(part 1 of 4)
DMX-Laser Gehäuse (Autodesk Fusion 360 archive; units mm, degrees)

design "Laser Gehäuse" references "Laserhalter", "Spiegelaufbau", "Leiterplatte", "Leiterplatte 3 Laser"
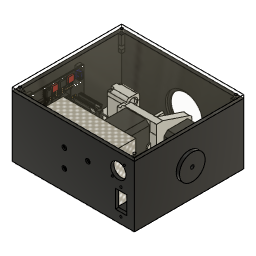
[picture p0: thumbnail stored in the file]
component_insert "Komponente einfügen1"
sketch "Skizze1" plane through (0, 0, 0) normal (0, 0, 1) x axis (1, 0, 0)
  line L1 (190, 0) -> (0, 0)
  line L2 (190, 150) -> (190, 0)
  line L3 (0, 150) -> (190, 150)
  line L4 (0, 0) -> (0, 150)
  point P1 (0, 0)
  point P2 (0, 0)
  horizontal L1
  vertical L2
  horizontal L3
  vertical L4
  coincident P1 P2
extrude "Extrusion1" new body sketch "Skizze1" along normal blind 5
sketch "Skizze2" plane through (0, 0, 5) normal (0, 0, 1) x axis (-1, 0, 0)
  line L1 (0, 0) -> (0, -150)
  line L2 (-190, 0) -> (0, 0)
  line L3 (-190, -150) -> (-190, 0)
  line L4 (0, -150) -> (-190, -150)
  line L5 (-190, 0) -> (0, 0)
  line L6 (-190, -150) -> (-190, 0)
  line L7 (0, -150) -> (-190, -150)
  line L8 (0, 0) -> (0, -150)
  line L9 (-185, -5) -> (-5, -5)
  line L10 (-185, -145) -> (-185, -5)
  line L11 (-5, -145) -> (-185, -145)
  line L12 (-5, -5) -> (-5, -145)
  point P5 (-190, -150)
  point P8 (-190, -150)
  point P1 (0, 0)
  point P6 (0, 0)
  horizontal L5
  vertical L6
  horizontal L7
  vertical L8
  coincident P5 P8
  coincident P1 P6
  horizontal L9
  vertical L10
  horizontal L11
  vertical L12
extrude "Extrusion2" add sketch "Skizze2" along normal blind 90
sketch "Skizze3" plane through (0, 0, 95) normal (0, 0, 1) x axis (-1, 0, 0)
  line L1 (-5, -145) -> (-5, -5)
  line L2 (-185, -145) -> (-5, -145)
  line L3 (-185, -5) -> (-185, -145)
  line L4 (-5, -5) -> (-185, -5)
  line L5 (0, 0) -> (0, -150)
  line L6 (-190, 0) -> (0, 0)
  line L7 (-190, -150) -> (-190, 0)
  line L8 (0, -150) -> (-190, -150)
  line L9 (-190, 0) -> (0, 0)
  line L10 (-190, -150) -> (-190, 0)
  line L11 (0, -150) -> (-190, -150)
  line L12 (0, 0) -> (0, -150)
  point P9 (-190, -150)
  point P12 (-190, -150)
  point P7 (0, 0)
  point P10 (0, 0)
  horizontal L9
  vertical L10
  horizontal L11
  vertical L12
  coincident P9 P12
  coincident P7 P10
extrude "Extrusion3" new body sketch "Skizze3" along normal blind 5
remove_instance "Exemplar entfernen"
sketch "Skizze4" plane through (0, 0, 95) normal (0, 0, 1) x axis (-1, 0, 0)
  line L1 (-5, -145) -> (-5, -5)
  line L2 (-185, -145) -> (-5, -145)
  line L3 (-185, -5) -> (-185, -145)
  line L4 (-5, -5) -> (-185, -5)
  line L5 (0, 0) -> (0, -150)
  line L6 (-190, 0) -> (0, 0)
  line L7 (-190, -150) -> (-190, 0)
  line L8 (0, -150) -> (-190, -150)
  line L9 (-180, -5) -> (-185, -5)
  line L10 (-180, -10) -> (-180, -5)
  line L11 (-185, -10) -> (-180, -10)
  line L12 (-185, -5) -> (-185, -10)
  line L13 (-180, -145) -> (-185, -145)
  line L14 (-180, -140) -> (-180, -145)
  line L15 (-185, -140) -> (-180, -140)
  line L16 (-185, -145) -> (-185, -140)
  line L17 (-10, -145) -> (-5, -145)
  line L18 (-10, -140) -> (-10, -145)
  line L19 (-5, -140) -> (-10, -140)
  line L20 (-5, -145) -> (-5, -140)
  line L21 (-10, -5) -> (-5, -5)
  line L22 (-10, -10) -> (-10, -5)
  line L23 (-5, -10) -> (-10, -10)
  line L24 (-5, -5) -> (-5, -10)
  point P5 (-185, -5)
  point P10 (-185, -5)
  point P4 (-185, -145)
  point P14 (-185, -145)
  point P3 (-5, -145)
  point P18 (-5, -145)
  point P2 (-5, -5)
  point P22 (-5, -5)
  horizontal L9
  vertical L10
  horizontal L11
  vertical L12
  coincident P5 P10
  horizontal L13
  vertical L14
  horizontal L15
  vertical L16
  coincident P4 P14
  horizontal L17
  vertical L18
  horizontal L19
  vertical L20
  coincident P3 P18
  horizontal L21
  vertical L22
  horizontal L23
  vertical L24
  coincident P2 P22
extrude "Extrusion4" add sketch "Skizze4" profile of L1 L2 L3 L4 L9 L10 L11 L12 L13 L14 L15 L16 L17 L18 L19 L20 L21 L22 L23 L24 against normal blind 25
sketch "Skizze5" plane through (0, 0, 95) normal (0, 0, 1) x axis (-1, 0, 0)
  line L1 (-5, -140) -> (-5, -10)
  line L2 (-10, -140) -> (-5, -140)
  line L3 (-10, -145) -> (-10, -140)
  line L4 (-180, -145) -> (-10, -145)
  line L5 (-180, -140) -> (-180, -145)
  line L6 (-185, -140) -> (-180, -140)
  line L7 (-185, -10) -> (-185, -140)
  line L8 (-180, -10) -> (-185, -10)
  line L9 (-180, -5) -> (-180, -10)
  line L10 (-10, -5) -> (-180, -5)
  line L11 (-10, -10) -> (-10, -5)
  line L12 (-5, -10) -> (-10, -10)
  line L13 (0, 0) -> (0, -150)
  line L14 (-190, 0) -> (0, 0)
  line L15 (-190, -150) -> (-190, 0)
  line L16 (0, -150) -> (-190, -150)
  line L17 (-2, -10) -> (-10, -10)
  line L18 (-2, -2) -> (-2, -10)
  line L19 (-10, -2) -> (-2, -2)
  line L20 (-10, -10) -> (-10, -2)
  line L21 (-2, -140) -> (-10, -140)
  line L22 (-2, -148) -> (-2, -140)
  line L23 (-10, -148) -> (-2, -148)
  line L24 (-10, -140) -> (-10, -148)
  line L25 (-188, -140) -> (-180, -140)
  line L26 (-188, -148) -> (-188, -140)
  line L27 (-180, -148) -> (-188, -148)
  line L28 (-180, -140) -> (-180, -148)
  line L29 (-188, -10) -> (-180, -10)
  line L30 (-188, -2) -> (-188, -10)
  line L31 (-180, -2) -> (-188, -2)
  line L32 (-180, -10) -> (-180, -2)
  point P13 (-10, -10)
  point P18 (-10, -10)
  point P4 (-10, -140)
  point P22 (-10, -140)
  point P7 (-180, -140)
  point P26 (-180, -140)
  point P10 (-180, -10)
  point P30 (-180, -10)
  horizontal L17
  vertical L18
  horizontal L19
  vertical L20
  coincident P13 P18
  horizontal L21
  vertical L22
  horizontal L23
  vertical L24
  coincident P4 P22
  horizontal L25
  vertical L26
  horizontal L27
  vertical L28
  coincident P7 P26
  horizontal L29
  vertical L30
  horizontal L31
  vertical L32
  coincident P10 P30
extrude "Extrusion5" new body sketch "Skizze5" profile of L2 L3 L5 L6 L8 L9 L11 L12 L17 L18 L19 L20 L21 L22 L23 L24 L25 L26 L27 L28 L29 L30 L31 L32 along normal blind 5
move "Verschieben1"
combine "Kombinieren1" sketch "Skizze7"
sketch "Skizze6" plane through (0, 0, 95) normal (0, 0, 1) x axis (-1, 0, 0)
  line L1 (-5, -140) -> (-5, -10)
  line L2 (-10, -140) -> (-5, -140)
  line L3 (-10, -145) -> (-10, -140)
  line L4 (-180, -145) -> (-10, -145)
  line L5 (-180, -140) -> (-180, -145)
  line L6 (-185, -140) -> (-180, -140)
  line L7 (-185, -10) -> (-185, -140)
  line L8 (-180, -10) -> (-185, -10)
  line L9 (-180, -5) -> (-180, -10)
  line L10 (-10, -5) -> (-180, -5)
  line L11 (-10, -10) -> (-10, -5)
  line L12 (-5, -10) -> (-10, -10)
  line L13 (0, 0) -> (0, -150)
  line L14 (-190, 0) -> (0, 0)
  line L15 (-190, -150) -> (-190, 0)
  line L16 (0, -150) -> (-190, -150)
  circle C1 centre (-184, -6) radius 2
  circle C2 centre (-6, -6) radius 2
  circle C3 centre (-6, -144) radius 2
  circle C4 centre (-184, -144) radius 2
  dimension "d11" diameter C2 = 4
  dimension "d12" diameter C3 = 4
  dimension "d13" diameter C4 = 4
extrude "Extrusion6" cut sketch "Skizze6" profile of C1 C2 C3 C4 against normal blind 18
extrude "Extrusion7" cut sketch "Skizze6" profile of C1 C2 C3 C4 along normal blind 20
sketch "Skizze7" plane through (5, 0, 0) normal (1, 0, 0) x axis (0, 1, 0)
  line L1 (5, 70) -> (10, 70)
  line L2 (5, 5) -> (5, 70)
  line L3 (145, 5) -> (5, 5)
  line L4 (145, 70) -> (145, 5)
  line L5 (140, 70) -> (145, 70)
  line L6 (140, 75) -> (140, 70)
  line L7 (140, 80) -> (140, 75)
  line L8 (140, 95) -> (140, 80)
  line L9 (10, 95) -> (140, 95)
  line L10 (10, 80) -> (10, 95)
  line L11 (10, 75) -> (10, 80)
  line L12 (10, 70) -> (10, 75)
  circle C1 centre (18.7202, 82.3008) radius 1.269
  circle C2 centre (18.7208, 12.447) radius 1.2684
  circle C3 centre (96.1888, 12.4478) radius 1.2703
  circle C4 centre (96.1914, 82.3004) radius 1.2677
extrude "Extrusion8" add sketch "Skizze7" profile of C1 C2 C3 C4 along normal blind 15
sketch "Skizze8" plane through (5, 0, 0) normal (1, 0, 0) x axis (0, 1, 0)
  line L1 (5, 70) -> (10, 70)
  line L2 (5, 5) -> (5, 70)
  line L3 (145, 5) -> (5, 5)
  line L4 (145, 70) -> (145, 5)
  line L5 (140, 70) -> (145, 70)
  line L6 (140, 75) -> (140, 70)
  line L7 (140, 80) -> (140, 75)
  line L8 (140, 95) -> (140, 80)
  line L9 (10, 95) -> (140, 95)
  line L10 (10, 80) -> (10, 95)
  line L11 (10, 75) -> (10, 80)
  line L12 (10, 70) -> (10, 75)
  line L13 (22.5, 9) -> (15, 9)
  line L14 (22.5, 16) -> (22.5, 9)
  line L15 (15, 16) -> (22.5, 16)
  line L16 (15, 9) -> (15, 16)
  line L17 (22.5, 86) -> (15, 86)
  line L18 (22.5, 78.1326) -> (22.5, 86)
  line L19 (15, 78.1326) -> (22.5, 78.1326)
  line L20 (15, 86) -> (15, 78.1326)
  line L21 (92.4144, 86) -> (100, 86)
  line L22 (92.4144, 78.1326) -> (92.4144, 86)
  line L23 (100, 78.1326) -> (92.4144, 78.1326)
  line L24 (100, 86) -> (100, 78.1326)
  line L25 (92.4144, 9) -> (100, 9)
  line L26 (92.4144, 15.9814) -> (92.4144, 9)
  line L27 (100, 15.9814) -> (92.4144, 15.9814)
  line L28 (100, 9) -> (100, 15.9814)
  circle C1 centre (18.7208, 12.447) radius 1.2684
  circle C2 centre (18.7202, 82.3008) radius 1.269
  circle C3 centre (96.1888, 12.4478) radius 1.2703
  circle C4 centre (96.1914, 82.3004) radius 1.2677
  horizontal L13
  vertical L14
  horizontal L15
  vertical L16
  horizontal L17
  vertical L18
  horizontal L19
  vertical L20
  horizontal L21
  vertical L22
  horizontal L23
  vertical L24
  horizontal L25
  vertical L26
  horizontal L27
  vertical L28
extrude "Extrusion9" add sketch "Skizze8" profile of C1 C2 C3 C4 L13 L14 L15 L16 L17 L18 L19 L20 L21 L22 L23 L24 L25 L26 L27 L28 along normal blind 4
component_insert "Komponente einfügen3"
extrude "Extrusion10" new body of existing geometry blind 5
extrude "Extrusion11" cut of existing geometry blind 77
sketch "Skizze9" plane through (0, 150, 0) normal (0, 1, 0) x axis (-1, 0, 0)
  line L1 (0, 0) -> (-190, 0)
  line L2 (0, 95) -> (0, 0)
  line L3 (-190, 95) -> (0, 95)
  line L4 (-190, 0) -> (-190, 95)
  line L5 (-102.1668, 34.55) -> (-102.1668, 49.55)
  circle C1 centre (-102.1668, 49.55) radius 2.5
  circle C2 centre (-102.1668, 34.55) radius 25
  point P2 (-102.1668, 49.55)
  point P7 (-102.1668, 49.55)
  point P8 (-102.1668, 34.55)
  point P9 (-102.1668, 34.55)
  coincident P2 P7
  vertical L5
  coincident P8 P9
  dimension "d26" distance P7 P8 = 15
  dimension "d27" diameter C2 = 50
extrude "Extrusion12" cut sketch "Skizze9" profile of C1 C2 against normal blind 5
sketch "Skizze10" plane through (0, 0, 5) normal (0, 0, 1) x axis (-1, 0, 0)
  line L1 (-185, -5) -> (-5, -5)
  line L2 (-185, -145) -> (-185, -5)
  line L3 (-5, -145) -> (-185, -145)
  line L4 (-5, -5) -> (-5, -145)
  line L5 (-112.5897, -145) -> (-112.5897, -105.336)
  point P7 (-112.5897, -145)
  vertical L5
  coincident L3 P7
position "Position1"
extrude "Extrusion14" cut of existing geometry blind -5
extrude "Extrusion15" new body of existing geometry blind 5
combine "Kombinieren2"
extrude "Extrusion16" cut of existing geometry blind -5
sketch "Skizze11" plane through (0, 0, 0) normal (0, 0, -1) x axis (1, 0, 0)
  line L1 (0, -150) -> (0, 0)
  line L2 (190, -150) -> (0, -150)
  line L3 (190, 0) -> (190, -150)
  line L4 (0, 0) -> (190, 0)
  circle C1 centre (71.3168, -79.9832) radius 1.75
  circle C2 centre (129.3168, -137.9832) radius 1.75
  circle C3 centre (143.7816, -65.5188) radius 1.75
  circle C4 centre (71.3168, -79.9832) radius 3.5
  circle C5 centre (143.7816, -65.5188) radius 3.5
  circle C6 centre (129.3168, -137.9832) radius 3.5
  concentric C1 C4
  concentric C3 C5
  concentric C2 C6
  dimension "d38" diameter C4 = 7
  dimension "d39" diameter C5 = 7
  dimension "d40" diameter C6 = 7
extrude "Extrusion17" cut sketch "Skizze11" profile of C1 C2 C3 C4 C5 C6 against normal blind 3
sketch "Skizze12" plane through (0, 0, 0) normal (1, 0, 0) x axis (0, 1, 0)
sketch "Skizze13" plane through (0, 0, 0) normal (0, 0, 1) x axis (1, 0, 0)
  line L1 (-128, 0) -> (-50, 0)
  line L2 (-128, -113) -> (-128, 0)
  line L3 (-50, -113) -> (-128, -113)
  line L4 (-50, 0) -> (-50, -113)
  point P2 (-50, 0)
  point P3 (-128, 0)
  point P5 (-50, -113)
  horizontal L1
  vertical L2
  horizontal L3
  vertical L4
  dimension "d43" distance P2 P3 = 78
  dimension "d44" distance P2 P5 = 113
extrude "Extrusion18" add sketch "Skizze13" along normal blind 38
move "Verschieben2"
sketch "Skizze14" plane through (0, 5, 0) normal (0, 1, 0) x axis (-1, 0, 0)
  line L1 (-10, 75) -> (-10, 70)
  line L2 (-10, 80) -> (-10, 75)
  line L3 (-10, 95) -> (-10, 80)
  line L4 (-180, 95) -> (-10, 95)
  line L5 (-180, 80) -> (-180, 95)
  line L6 (-180, 75) -> (-180, 80)
  line L7 (-180, 70) -> (-180, 75)
  line L8 (-185, 70) -> (-180, 70)
  line L9 (-185, 5) -> (-185, 70)
  line L10 (-5, 5) -> (-185, 5)
  line L11 (-5, 70) -> (-5, 5)
  line L12 (-10, 70) -> (-5, 70)
  line L13 (-90, 75) -> (-100, 75)
  line L14 (-90, 65) -> (-90, 75)
  line L15 (-100, 65) -> (-90, 65)
  line L16 (-100, 75) -> (-100, 65)
  horizontal L13
  vertical L14
  horizontal L15
  vertical L16
extrude "Extrusion19" add sketch "Skizze14" profile of L13 L14 L15 L16 along normal blind 5
split "Teilen1"
extrude "Extrusion20" cut of existing geometry blind -5
move "Verschieben3"
move "Verschieben4"
split "Teilen2"
move "Verschieben5"
extrude "Extrusion21" add of existing geometry blind 20
move "Verschieben6"
split "Teilen3"
combine "Kombinieren3"
sketch "Skizze15" plane through (102.1668, 0, 0) normal (-1, 0, 0) x axis (0, -1, 0)
  line L1 (-98.9832, 45.05) -> (-115.9832, 45.05)
  line L2 (-98.9832, 46.85) -> (-98.9832, 45.05)
  line L3 (-98.9832, 51.55) -> (-98.9832, 46.85)
  line L4 (-98.9832, 54.05) -> (-98.9832, 51.55)
  line L5 (-115.9832, 54.05) -> (-98.9832, 54.05)
  line L6 (-115.9832, 45.05) -> (-115.9832, 54.05)
  line L7 (-98.9832, 45.05) -> (-98.9832, 54.05)
  line L8 (-98.9832, 49.55) -> (-98.9832, 45.05)
  line L9 (-115.9832, 49.55) -> (-98.9832, 49.55)
  line L10 (-107.4832, 5) -> (-107.4832, 49.55)
  point P6 (-98.9832, 54.05)
  point P8 (-98.9832, 54.05)
  point P3 (-98.9832, 45.05)
  point P9 (-98.9832, 45.05)
  point P10 (-98.9832, 45.05)
  point P11 (-98.9832, 49.55)
  point P12 (-115.9832, 49.55)
  point P13 (-107.4832, 49.55)
  coincident P6 P8
  coincident P3 P9
  coincident P3 P10
  midpoint L7 P11
  midpoint L6 P12
  midpoint L9 P13
  perpendicular L1 L10
split "Teilen4"
move "Verschieben7"
extrude "Extrusion22" add of existing geometry blind 20
sketch "Skizze16" plane through (0, -20, 0) normal (0, -1, 0) x axis (1, 0, 0)
  line L1 (66, 95) -> (66, 0)
  line L2 (0, 95) -> (66, 95)
  line L3 (0, 0) -> (0, 95)
  line L4 (66, 0) -> (0, 0)
  line L5 (160.5, 16) -> (178, 16)
  line L6 (160.5, 44) -> (160.5, 16)
  line L7 (178, 44) -> (160.5, 44)
  line L8 (178, 16) -> (178, 44)
  line L9 (169, 44) -> (178, 44)
  line L10 (169, 11) -> (169, 52.9725)
  line L11 (169, 49.8326) -> (169, 29.8326)
  line L12 (169, 9.8326) -> (169, 29.8326)
  circle C1 centre (169, 49.8326) radius 1.75
  circle C2 centre (169, 9.8326) radius 1.75
  point P13 (169, 29.8326)
  point P14 (169, 49.8326)
  point P16 (169, 49.8326)
  point P15 (169, 9.8326)
  point P17 (169, 9.8326)
  point P6 (178, 16)
  point P7 (160.5, 16)
  point P9 (178, 44)
  point P10 (169, 44)
  perpendicular L8 L9
  perpendicular L5 L10
  coincident L10 P13
  perpendicular L9 L11
  parallel L10 L12
  coincident P14 P16
  coincident P15 P17
  dimension "d55" distance P6 P7 = 17.5
  dimension "d56" distance P6 P9 = 28
  dimension "d57" distance P9 P10 = 9
  dimension "d58" distance P13 P14 = 20
  dimension "d59" distance P13 P15 = 20
  dimension "d60" diameter C1 = 3.5
  dimension "d61" diameter C2 = 3.5
move "Verschieben8"
move "Verschieben9"
extrude "Extrusion23" cut sketch "Skizze16" profile of L5 L6 L7 L8 L9 L10 L11 L12 C1 C2 against normal blind 5
sketch "Skizze17" plane through (0, -20, 0) normal (0, -1, 0) x axis (1, 0, 0)
  line L1 (66, 95) -> (66, 0)
  line L2 (0, 95) -> (66, 95)
  line L3 (0, 0) -> (0, 95)
  line L4 (66, 0) -> (0, 0)
  line L5 (20, 49) -> (0, 49)
  line L6 (12, 46) -> (12, 49)
  point P6 (0, 49)
  point P8 (12, 49)
  coincident L3 P6
  perpendicular L3 L5
  coincident L5 P8
  perpendicular L5 L6
sketch "Skizze18" plane through (190, 0, 0) normal (1, 0, 0) x axis (0, 1, 0)
  line L1 (150, 0) -> (-20, 0)
  line L2 (150, 95) -> (150, 0)
  line L3 (-20, 95) -> (150, 95)
  line L4 (-20, 0) -> (-20, 95)
  line L5 (150, 0) -> (-20, 95)
  line L6 (-20, 0) -> (150, 95)
  circle C1 centre (65, 47.5) radius 20
  point P5 (-20, 95)
  point P6 (-20, 95)
  point P3 (150, 0)
  point P7 (150, 0)
  point P4 (150, 95)
  point P8 (150, 95)
  point P2 (-20, 0)
  point P9 (-20, 0)
  point P10 (65, 47.5)
  coincident P5 P6
  coincident P3 P7
  coincident P4 P8
  coincident P2 P9
  midpoint L6 P10
  dimension "d64" diameter C1 = 40
extrude "Extrusion24" add sketch "Skizze18" profile of L5 L6 C1 along normal blind 5
sketch "Skizze19" plane through (0, 0, 0) normal (-1, 0, 0) x axis (0, -1, 0)
  line L1 (-150, 95) -> (20, 95)
  line L2 (-150, 0) -> (-150, 95)
  line L3 (20, 0) -> (-150, 0)
  line L4 (20, 95) -> (20, 0)
  line L5 (20, 0) -> (-150, 95)
  line L6 (-150, 0) -> (20, 95)
  circle C1 centre (-65, 47.5) radius 20
  point P3 (-150, 95)
  point P6 (-150, 95)
  point P5 (20, 0)
  point P7 (20, 0)
  point P2 (20, 95)
  point P8 (20, 95)
  point P4 (-150, 0)
  point P9 (-150, 0)
  point P10 (-65, 47.5)
  coincident P3 P6
  coincident P5 P7
  coincident P2 P8
  coincident P4 P9
  midpoint L5 P10
  dimension "d67" diameter C1 = 40
extrude "Extrusion25" add sketch "Skizze19" profile of L5 L6 C1 along normal blind 5
split "Teilen5"
combine "Kombinieren4"
move "Verschieben10"
sketch "Skizze20" plane through (0, 0, 5) normal (0, 0, 1) x axis (-1, 0, 0)
  line L1 (-66, -145) -> (-185, -145)
  line L2 (-66, 15) -> (-66, -145)
  line L3 (-185, 15) -> (-66, 15)
  line L4 (-185, -145) -> (-185, 15)
  circle C1 centre (-143.7816, -65.5188) radius 1.75
  circle C2 centre (-129.3168, -137.9832) radius 1.75
  circle C3 centre (-71.3168, -79.9832) radius 1.75
  circle C4 centre (-71.3168, -79.9832) radius 1.75
  circle C5 centre (-143.7816, -65.5188) radius 1.75
  circle C6 centre (-129.3168, -137.9832) radius 1.75
  concentric C3 C4
  concentric C1 C5
  concentric C2 C6
extrude "Extrusion26" add sketch "Skizze20" profile of C1 C2 C3 C4 C5 C6 against normal blind 5
extrude "Extrusion27" add of existing geometry blind 3
move "Verschieben11"
position "Position2"
sketch "Skizze21" plane through (110.1668, 0, 0) normal (-1, 0, 0) x axis (0, -1, 0)
  line L1 (-100.8991, 36.25) -> (-104.7673, 36.25)
  line L2 (-98.3332, 34.55) -> (-100.2582, 34.55)
  line L3 (-105.4082, 34.55) -> (-107.3332, 34.55)
  line L4 (-145, 9.5) -> (-145, 59.5)
  line L5 (-150, 59.5) -> (-145, 59.5)
  line L6 (-150, 9.5) -> (-145, 9.5)
  line L7 (-102.8332, 34.55) -> (-150, 9.5)
  line L8 (-150, 59.5) -> (-102.8332, 34.55)
  arc A1 centre (-102.8332, 34.55) radius 2.575 clockwise from (-105.4082, 34.55) to (-104.7673, 36.25)
  arc A2 centre (-102.8332, 34.55) radius 2.575 clockwise from (-100.8991, 36.25) to (-100.2582, 34.55)
  arc A3 centre (-102.8332, 34.55) radius 4.5 clockwise from (-107.3332, 34.55) to (-98.3332, 34.55)
  point P4 (-102.8332, 34.55)
  point P13 (-102.8332, 34.55)
  point P9 (-145, 59.5)
  point P10 (-145, 9.5)
  perpendicular L4 L5
  perpendicular L4 L6
  coincident P4 P13
  dimension "d74" distance P9 P10 = 50
sketch "Skizze22" plane through (0, 145, 0) normal (0, -1, 0) x axis (1, 0, 0)
  line L1 (66, 5) -> (66, 95)
  line L2 (185, 5) -> (66, 5)
  line L3 (185, 70) -> (185, 5)
  line L4 (180, 70) -> (185, 70)
  line L5 (180, 75) -> (180, 70)
  line L6 (180, 80) -> (180, 75)
  line L7 (180, 95) -> (180, 80)
  line L8 (66, 95) -> (180, 95)
  circle C1 centre (102.1668, 34.55) radius 25
  circle C2 centre (102.1668, 34.55) radius 29
  concentric C1 C2
  dimension "d75" diameter C2 = 58
extrude "Extrusion28" cut sketch "Skizze22" profile of C1 C2 against normal blind 3
sketch "Skizze23" plane through (0, 150, 0) normal (0, 1, 0) x axis (-1, 0, 0)
  line L1 (-190, 0) -> (-190, 95)
  line L2 (-66, 0) -> (-190, 0)
  line L3 (-66, 95) -> (-66, 0)
  line L4 (-190, 95) -> (-66, 95)
  line L5 (-131.1668, 0) -> (-131.1668, 34.55)
  line L6 (-73.1668, 0) -> (-73.1668, 34.55)
  line L7 (-131.1668, 5) -> (-131.1668, 0)
  line L8 (-67, 5) -> (-142, 5)
  line L9 (-135.4094, 9.2426) -> (-131.1668, 5)
  line L10 (-125.1668, 5) -> (-131.1668, 5)
  line L11 (-68.9241, 9.2426) -> (-73.1668, 5)
  line L12 (-67.1668, 5) -> (-73.1668, 5)
  circle C1 centre (-102.1668, 34.55) radius 25
  circle C2 centre (-102.1668, 34.55) radius 29
  circle C3 centre (-135.4094, 9.2426) radius 1.75
  circle C4 centre (-68.9241, 9.2426) radius 1.75
  point P8 (-131.1668, 34.55)
  point P9 (-131.1668, 0)
  point P10 (-73.1668, 34.55)
  point P11 (-73.1668, 0)
  point P12 (-131.1668, 5)
  point P17 (-73.1668, 5)
  point P15 (-135.4094, 9.2426)
  point P20 (-135.4094, 9.2426)
  point P18 (-68.9241, 9.2426)
  point P21 (-68.9241, 9.2426)
  concentric C1 C2
  coincident C2 P8
  coincident L2 P9
  tangent C2 L5
  perpendicular L2 L5
  coincident C2 P10
  coincident L2 P11
  tangent C2 L6
  perpendicular L2 L6
  coincident L5 P12
  perpendicular L3 L8
  horizontal L10
  horizontal L12
  coincident L8 P17
  coincident L6 P17
  coincident P15 P20
  coincident P18 P21
  dimension "d78" diameter C2 = 58
  dimension "d79" angle L9 L10 = 135
  dimension "d80" distance P12 P15 = 6
  dimension "d81" angle L11 L12 = 45
  dimension "d82" distance P17 P18 = 6
  dimension "d83" diameter C3 = 3.5
  dimension "d84" diameter C4 = 3.5
extrude "Extrusion29" cut sketch "Skizze23" profile of C3 C4 against normal blind 5
extrude "Extrusion30" cut of existing geometry blind -200
sketch "Skizze24" plane through (9, 0, 0) normal (1, 0, 0) x axis (0, 1, 0)
  line L1 (2.5, 78.1326) -> (-5, 78.1326)
  line L2 (2.5, 86) -> (2.5, 78.1326)
  line L3 (-5, 86) -> (2.5, 86)
  line L4 (-5, 78.1326) -> (-5, 86)
  circle C1 centre (-1.2798, 82.3008) radius 1.269
  circle C2 centre (-1.2798, 82.3008) radius 1.55
  concentric C1 C2
  dimension "d89" diameter C2 = 3.1
extrude "Extrusion31" cut sketch "Skizze24" profile of C1 C2 against normal blind 20
sketch "Skizze25" plane through (9, 0, 0) normal (1, 0, 0) x axis (0, 1, 0)
  line L1 (-5, 9) -> (-5, 16)
  line L2 (2.5, 9) -> (-5, 9)
  line L3 (2.5, 16) -> (2.5, 9)
  line L4 (-5, 16) -> (2.5, 16)
  circle C1 centre (-1.2792, 12.447) radius 1.2684
  circle C2 centre (-1.2792, 12.447) radius 1.55
  concentric C1 C2
  dimension "d92" diameter C2 = 3.1
extrude "Extrusion32" cut sketch "Skizze25" profile of C1 C2 against normal blind 20
sketch "Skizze26" plane through (9, 0, 0) normal (1, 0, 0) x axis (0, 1, 0)
  line L1 (72.4144, 15.9814) -> (80, 15.9814)
  line L2 (72.4144, 9) -> (72.4144, 15.9814)
  line L3 (80, 9) -> (72.4144, 9)
  line L4 (80, 15.9814) -> (80, 9)
  circle C1 centre (76.1888, 12.4478) radius 1.2703
  circle C2 centre (76.1888, 12.4478) radius 1.55
  concentric C1 C2
  dimension "d95" diameter C2 = 3.1
extrude "Extrusion33" cut sketch "Skizze26" profile of C1 C2 against normal blind 20
sketch "Skizze27" plane through (9, 0, 0) normal (1, 0, 0) x axis (0, 1, 0)
  line L1 (80, 86) -> (80, 78.1326)
  line L2 (72.4144, 86) -> (80, 86)
  line L3 (72.4144, 78.1326) -> (72.4144, 86)
  line L4 (80, 78.1326) -> (72.4144, 78.1326)
  circle C1 centre (76.1914, 82.3004) radius 1.2677
  circle C2 centre (76.1914, 82.3004) radius 1.55
  concentric C1 C2
  dimension "d98" diameter C2 = 3.1
extrude "Extrusion34" cut sketch "Skizze27" profile of C1 C2 against normal blind 20
sketch "Skizze28" plane through (0, 0, 0) normal (-1, 0, 0) x axis (0, -1, 0)
  line L1 (-150, 95) -> (20, 95)
  line L2 (-150, 0) -> (-150, 95)
  line L3 (20, 0) -> (-150, 0)
  line L4 (20, 95) -> (20, 0)
  circle C1 centre (-76.1914, 82.3004) radius 1.55
  circle C2 centre (-76.1888, 12.4478) radius 1.55
  circle C3 centre (1.2792, 12.447) radius 1.55
  circle C4 centre (1.2798, 82.3008) radius 1.55
  circle C5 centre (-65, 47.5) radius 20
  circle C6 centre (-76.1914, 82.3004) radius 3.5
  circle C7 centre (-76.1888, 12.4478) radius 3.5
  circle C8 centre (1.2798, 82.3008) radius 3.5
  circle C9 centre (1.2792, 12.447) radius 3.5
  concentric C1 C6
  concentric C2 C7
  concentric C4 C8
  concentric C3 C9
  dimension "d101" diameter C6 = 7
  dimension "d102" diameter C7 = 7
  dimension "d103" diameter C8 = 7
  dimension "d104" diameter C9 = 7
extrude "Extrusion35" cut sketch "Skizze28" profile of C1 C2 C3 C4 C6 C7 C8 C9 against normal blind 3
sketch "Skizze29" plane through (0, -15, 0) normal (0, -1, 0) x axis (1, 0, 0)
  line L1 (36, 84) -> (149, 84)
  line L2 (36, 6) -> (36, 84)
  line L3 (149, 6) -> (36, 6)
  line L4 (149, 84) -> (149, 6)
  line L5 (117.5, 84) -> (149, 84)
  line L6 (149, 2.669) -> (117.5, 2.669)
  line L7 (149, 84) -> (149, 2.669)
  line L8 (81, 84) -> (117.5, 84)
  line L9 (117.5, 2.9178) -> (81, 2.9178)
  line L10 (155, 84) -> (36, 84)
  line L11 (155, 59) -> (155, 84)
  line L12 (36, 84) -> (36, 59)
  line L13 (53.6929, 31) -> (53.6929, 59)
  line L14 (155, 59) -> (155, 31)
  line L15 (81, 60.75) -> (81, 84)
  line L16 (36, 59) -> (79.25, 59)
  line L17 (53.6929, 59) -> (79.25, 59)
  line L18 (119.25, 59) -> (155, 59)
  line L19 (82.75, 59) -> (115.75, 59)
  line L20 (119.25, 59) -> (155, 59)
  line L21 (82.75, 59) -> (115.75, 59)
  line L22 (117.5, 60.75) -> (117.5, 84)
  line L23 (117.5, 2.669) -> (117.5, 57.25)
  line L24 (117.5, 57.25) -> (117.5, 2.9178)
  line L25 (117.5, 84) -> (117.5, 60.75)
  line L26 (81, 32.75) -> (81, 57.25)
  line L27 (81, 2.9178) -> (81, 29.25)
  line L28 (79.25, 31) -> (53.6929, 31)
  line L29 (155, 31) -> (82.75, 31)
  circle C1 centre (81, 59) radius 1.75
  circle C2 centre (117.5, 59) radius 1.75
  circle C3 centre (81, 31) radius 1.75
  point P2 (149, 84)
  point P6 (149, 84)
  point P3 (36, 84)
  point P13 (36, 84)
  point P20 (81, 59)
  point P21 (117.5, 59)
  point P22 (81, 31)
  point P23 (81, 60.75)
  point P24 (81, 57.25)
  point P25 (82.75, 59)
  point P26 (79.25, 59)
  point P27 (115.75, 59)
  point P28 (119.25, 59)
  point P29 (117.5, 60.75)
  point P30 (117.5, 57.25)
  point P31 (81, 29.25)
  point P32 (79.25, 31)
  point P33 (82.75, 31)
  point P34 (81, 32.75)
  point P7 (117.5, 84)
  point P10 (81, 84)
  point P16 (36, 59)
  point P15 (155, 59)
  point P19 (155, 31)
  horizontal L5
  vertical L22
  horizontal L6
  vertical L7
  coincident P2 P6
  horizontal L8
  vertical L15
  horizontal L9
  vertical L24
  horizontal L10
  vertical L11
  horizontal L20
  vertical L12
  coincident P3 P13
  horizontal L18
  vertical L13
  horizontal L28
  vertical L14
  coincident P20 L18
  coincident P21 L24
  coincident P21 L20
  coincident P22 L15
  coincident P22 L28
  coincident C1 P23
  collinear L15 L26
  coincident C1 P24
  coincident C1 P25
  coincident C1 P26
  collinear L16 L20
  collinear L17 L18
  coincident C2 P27
  collinear L18 L19
  coincident C2 P28
  collinear L20 L21
  coincident C2 P29
  coincident C2 P30
  collinear L22 L23
  collinear L24 L25
  coincident C3 P31
  collinear L26 L27
  coincident C3 P32
  collinear L28 L29
  coincident C3 P33
  coincident C3 P34
  dimension "d107" distance P6 P7 = 31.5
  dimension "d108" distance P7 P10 = 36.5
  dimension "d109" distance P13 P16 = 25
  dimension "d110" distance P15 P19 = 28
  dimension "d111" diameter C1 = 3.5
  dimension "d112" diameter C2 = 3.5
  dimension "d113" diameter C3 = 3.5
extrude "Extrusion36" cut sketch "Skizze29" profile of C1 C2 C3 along normal blind 40
sketch "Skizze30" plane through (0, -20, 0) normal (0, -1, 0) x axis (1, 0, 0)
  line L1 (178, 44) -> (160.5, 44)
  line L2 (178, 16) -> (178, 44)
  line L3 (160.5, 16) -> (178, 16)
  line L4 (160.5, 44) -> (160.5, 16)
  line L5 (66, 0) -> (66, 95)
  line L6 (190, 0) -> (66, 0)
  line L7 (190, 95) -> (190, 0)
  line L8 (66, 95) -> (190, 95)
  circle C1 centre (81, 59) radius 1.75
  circle C2 centre (117.5, 59) radius 1.75
  circle C3 centre (81, 31) radius 1.75
  circle C4 centre (169, 9.8326) radius 1.75
  circle C5 centre (169, 49.8326) radius 1.75
  circle C6 centre (81, 59) radius 3.5
  circle C7 centre (117.5, 59) radius 3.5
  circle C8 centre (81, 31) radius 3.5
  concentric C1 C6
  concentric C2 C7
  concentric C3 C8
  dimension "d116" diameter C6 = 7
  dimension "d117" diameter C7 = 7
  dimension "d118" diameter C8 = 7
extrude "Extrusion37" cut sketch "Skizze30" profile of C1 C2 C3 C6 C7 C8 against normal blind 2
sketch "Skizze31" plane through (0, 0, 5) normal (0, 0, 1) x axis (-1, 0, 0)
  line L1 (-66, -145) -> (-66, 15)
  line L2 (-5, -145) -> (-66, -145)
  line L3 (-5, 15) -> (-5, -145)
  line L4 (-66, 15) -> (-5, 15)
  line L5 (-65, -135) -> (-18, -135)
  line L6 (-65, -85) -> (-65, -117)
  line L7 (-18, -85) -> (-42, -85)
  line L8 (-15, -132) -> (-15, -88)
  line L9 (-45, -48) -> (-45, -82)
  line L10 (-62, -45) -> (-48, -45)
  line L11 (-65, -85) -> (-65, -48)
  line L12 (-77, -135) -> (-65, -135)
  line L13 (-80, -123) -> (-80, -132)
  line L14 (-68, -120) -> (-77, -120)
  arc A1 centre (-77, -132) radius 3 clockwise from (-77, -135) to (-80, -132)
  arc A2 centre (-77, -123) radius 3 clockwise from (-80, -123) to (-77, -120)
  arc A3 centre (-68, -117) radius 3 clockwise from (-65, -117) to (-68, -120)
  arc A4 centre (-62, -48) radius 3 clockwise from (-65, -48) to (-62, -45)
  arc A5 centre (-48, -48) radius 3 clockwise from (-48, -45) to (-45, -48)
  arc A6 centre (-42, -82) radius 3 clockwise from (-42, -85) to (-45, -82)
  arc A7 centre (-18, -88) radius 3 clockwise from (-18, -85) to (-15, -88)
  arc A8 centre (-18, -132) radius 3 clockwise from (-15, -132) to (-18, -135)
  circle C1 centre (-20, -130) radius 1.75
  circle C2 centre (-75, -127.5) radius 1.75
  circle C3 centre (-20, -90) radius 1.75
  circle C4 centre (-50, -50) radius 1.75
  circle C5 centre (-60, -50) radius 1.75
  circle C6 centre (-60, -90) radius 1.75
  point P12 (-80, -135)
  point P13 (-65, -120)
  point P11 (-65, -45)
  point P10 (-45, -85)
  point P9 (-15, -85)
  point P6 (-15, -135)
  point P7 (-65, -135)
  point P8 (-65, -85)
  horizontal L5
  vertical L6
  horizontal L7
  vertical L8
  vertical L9
  horizontal L10
  vertical L11
  horizontal L12
  vertical L13
  horizontal L14
  coincident P12 L12
  coincident P12 L13
  tangent L12 A1
  tangent L13 A1
  tangent L13 A2
  tangent L14 A2
  equal A1 A2
  coincident P13 L14
  coincident L6 P13
  tangent L14 A3
  tangent L6 A3
  equal A1 A3
  coincident P11 L10
  coincident P11 L11
  tangent L10 A4
  tangent L11 A4
  equal A1 A4
  tangent L9 A5
  tangent L10 A5
  equal A1 A5
  coincident P10 L9
  coincident L7 P10
  tangent L9 A6
  tangent L7 A6
  equal A1 A6
  coincident P9 L7
  coincident P9 L8
  tangent L7 A7
  tangent L8 A7
  equal A1 A7
  coincident P6 L5
  coincident P6 L8
  tangent L5 A8
  tangent L8 A8
  equal A1 A8
  dimension "d121" distance P6 P7 = 50
  dimension "d122" distance P6 P9 = 50
  dimension "d123" distance P8 P10 = 20
  dimension "d124" distance P8 P11 = 40
  dimension "d125" distance P7 P12 = 15
  dimension "d126" distance P7 P13 = 15
  dimension "d127" radius A1 = 3
  dimension "d128" diameter C1 = 3.5
  dimension "d129" diameter C2 = 3.5
  dimension "d130" diameter C3 = 3.5
  dimension "d131" diameter C4 = 3.5
  dimension "d132" diameter C5 = 3.5
  dimension "d133" diameter C6 = 3.5
extrude "Extrusion38" new body sketch "Skizze31" profile of L1 L5 L6 L7 L8 L9 L10 L11 L12 L13 L14 A1 A2 A3 A4 A5 A6 A7 A8 C1 C2 C3 C4 C5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 along normal blind 5
combine "Kombinieren5"
extrude "Extrusion39" cut of existing geometry blind -6
sketch "Skizze32" plane through (0, 0, 0) normal (0, 0, -1) x axis (1, 0, 0)
  line L1 (190, -150) -> (0, -150)
  line L2 (190, 20) -> (190, -150)
  line L3 (0, 20) -> (190, 20)
  line L4 (0, -150) -> (0, 20)
  circle C1 centre (20, -90) radius 1.75
  circle C2 centre (129.3168, -132.9832) radius 1.75
  circle C3 centre (50, -50) radius 1.75
  circle C4 centre (71.3168, -74.9832) radius 1.75
  circle C5 centre (143.7816, -60.5188) radius 1.75
  circle C6 centre (60, -50) radius 1.75
  circle C7 centre (60, -90) radius 1.75
  circle C8 centre (75, -127.5) radius 1.75
  circle C9 centre (20, -130) radius 1.75
  circle C10 centre (60, -50) radius 3.5
  circle C11 centre (50, -50) radius 3.5
  circle C12 centre (71.3168, -74.9832) radius 3.5
  circle C13 centre (60, -90) radius 3.5
  circle C14 centre (20, -90) radius 3.5
  circle C15 centre (20, -130) radius 3.5
  circle C16 centre (75, -127.5) radius 3.5
  circle C17 centre (129.3168, -132.9832) radius 3.5
  circle C18 centre (143.7816, -60.5188) radius 3.5
  concentric C6 C10
  concentric C3 C11
  concentric C4 C12
  concentric C7 C13
  concentric C1 C14
  concentric C9 C15
  concentric C8 C16
  concentric C2 C17
  concentric C5 C18
  dimension "d138" diameter C10 = 7
  dimension "d139" diameter C11 = 7
  dimension "d140" diameter C12 = 7
  dimension "d141" diameter C13 = 7
  dimension "d142" diameter C14 = 7
  dimension "d143" diameter C15 = 7
  dimension "d144" diameter C16 = 7
  dimension "d145" diameter C17 = 7
  dimension "d146" diameter C18 = 7
extrude "Extrusion40" cut sketch "Skizze32" profile of C1 C2 C3 C4 C5 C6 C7 C8 C9 C10 C11 C12 C13 C14 C15 C16 C17 C18 against normal blind 3
sketch "Skizze33" plane through (-5, 0, 0) normal (-1, 0, 0) x axis (0, -1, 0)
  circle C1 centre (-65, 47.5) radius 20
  circle C2 centre (-65, 47.5) radius 2.75
  concentric C1 C2
  dimension "d149" diameter C2 = 5.5
extrude "Extrusion41" cut sketch "Skizze33" profile of C2 against normal blind 1000000
sketch "Skizze34" plane through (0, -20, 0) normal (0, -1, 0) x axis (1, 0, 0)
  line L1 (178, 44) -> (160.5, 44)
  line L2 (178, 16) -> (178, 44)
  line L3 (160.5, 16) -> (178, 16)
  line L4 (160.5, 44) -> (160.5, 16)
  line L5 (190, 0) -> (0, 0)
  line L6 (190, 95) -> (190, 0)
  line L7 (0, 95) -> (190, 95)
  line L8 (0, 0) -> (0, 95)
  line L9 (169, 57) -> (169, 9.8326)
  line L10 (169, 92) -> (169, 57)
  line L11 (148, 58) -> (165, 58)
  line L12 (180, 82) -> (165, 82)
  line L13 (155.5, 58) -> (165, 58)
  line L14 (174.5, 82) -> (165, 82)
  circle C1 centre (81, 59) radius 3.5
  circle C2 centre (117.5, 59) radius 3.5
  circle C3 centre (81, 31) radius 3.5
  circle C4 centre (169, 9.8326) radius 1.75
  circle C5 centre (169, 49.8326) radius 1.75
  circle C6 centre (165, 70) radius 12
  circle C7 centre (155.5, 58) radius 1.55
  circle C8 centre (174.5, 82) radius 1.55
  point P5 (169, 9.8326)
  point P15 (169, 9.8326)
  point P19 (165, 58)
  point P21 (165, 82)
  point P23 (155.5, 58)
  point P25 (155.5, 58)
  point P24 (174.5, 82)
  point P26 (174.5, 82)
  coincident P5 P15
  perpendicular L1 L9
  perpendicular L1 L10
  coincident C6 P19
  perpendicular L10 L11
  coincident C6 P21
  perpendicular L10 L12
  parallel L11 L13
  parallel L12 L14
  coincident P23 P25
  coincident P24 P26
  dimension "d153" diameter C6 = 24
  dimension "d154" distance P19 P23 = 9.5
  dimension "d155" distance P21 P24 = 9.5
  dimension "d156" diameter C7 = 3.1
  dimension "d157" diameter C8 = 3.1
extrude "Extrusion42" cut sketch "Skizze34" profile of L10 C6 L11 L12 L13 L14 C7 C8 against normal blind 5
sketch "Skizze35" plane through (0, 0, 10) normal (0, 0, 1) x axis (-1, 0, 0)
  line L1 (-18, -135) -> (-77, -135)
  line L2 (-15, -88) -> (-15, -132)
  line L3 (-42, -85) -> (-18, -85)
  line L4 (-45, -48) -> (-45, -82)
  line L5 (-62, -45) -> (-48, -45)
  line L6 (-65, -117) -> (-65, -48)
  line L7 (-77, -120) -> (-68, -120)
  line L8 (-80, -132) -> (-80, -123)
  line L9 (-15, -103) -> (-110, -103)
  line L10 (-60, -103) -> (-60, -135)
  circle C1 centre (-75, -127.5) radius 1.75
  circle C2 centre (-60, -50) radius 1.75
  circle C3 centre (-20, -130) radius 1.75
  circle C4 centre (-50, -50) radius 1.75
  circle C5 centre (-60, -90) radius 1.75
  circle C6 centre (-20, -90) radius 1.75
  arc A1 centre (-18, -132) radius 3 clockwise from (-15, -132) to (-18, -135)
  arc A2 centre (-18, -88) radius 3 clockwise from (-18, -85) to (-15, -88)
  arc A3 centre (-42, -82) radius 3 clockwise from (-42, -85) to (-45, -82)
  arc A4 centre (-48, -48) radius 3 clockwise from (-48, -45) to (-45, -48)
  arc A5 centre (-62, -48) radius 3 clockwise from (-65, -48) to (-62, -45)
  arc A6 centre (-68, -117) radius 3 clockwise from (-65, -117) to (-68, -120)
  arc A7 centre (-77, -123) radius 3 clockwise from (-80, -123) to (-77, -120)
  arc A8 centre (-77, -132) radius 3 clockwise from (-77, -135) to (-80, -132)
  point P33 (-15, -103)
  point P34 (-60, -135)
  point P35 (-60, -103)
  coincident L2 P33
  perpendicular L2 L9
  coincident L1 P34
  coincident L9 P35
  perpendicular L9 L10
component_insert "Komponente einfügen6"
component_insert "Komponente einfügen7"
extrude "Extrusion44" new body of existing geometry blind 8
sketch "Skizze36" plane through (195, 0, 0) normal (1, 0, 0) x axis (0, 1, 0)
  line L1 (85, 47.5) -> (45, 47.5)
  line L2 (85, 147.5) -> (85, 47.5)
  line L3 (45, 147.5) -> (85, 147.5)
  line L4 (45, 47.5) -> (45, 147.5)
  line L5 (85, 147.5) -> (45, 147.5)
  line L6 (85, 152.5) -> (85, 147.5)
  line L7 (45, 152.5) -> (85, 152.5)
  line L8 (45, 147.5) -> (45, 152.5)
  circle C1 centre (65, 47.5) radius 2.75
  circle C2 centre (65, 47.5) radius 20
  circle C3 centre (65, 47.5) radius 2.75
  circle C4 centre (65, 47.5) radius 20
  point P5 (45, 47.5)
  point P6 (85, 47.5)
  point P8 (45, 147.5)
  point P11 (45, 152.5)
  concentric C1 C3
  concentric C3 C4
  horizontal L1
  vertical L2
  horizontal L3
  vertical L4
  coincident C4 P5
  horizontal L5
  vertical L6
  horizontal L7
  vertical L8
  dimension "d164" distance P5 P6 = 40
  dimension "d165" distance P5 P8 = 100
  dimension "d166" distance P8 P11 = 5
extrude "Extrusion45" new body sketch "Skizze36" along normal blind 5
extrude "Extrusion46" new body sketch "Skizze36" profile of L3 L5 L6 L7 L8 against normal blind 200
copy_paste_bodies "Körper kopieren/einfügen"
move "Verschieben12"
combine "Kombinieren6"
sketch "Skizze37" plane through (0, 0, 152.5) normal (0, 0, 1) x axis (-1, 0, 0)
  line L1 (10, -45) -> (10, -85)
  line L2 (-200, -45) -> (10, -45)
  line L3 (-200, -85) -> (-200, -45)
  line L4 (10, -85) -> (-200, -85)
  line L5 (-45, -65) -> (-95, -65)
  line L6 (-145, -65) -> (-95, -65)
  circle C1 centre (-95, -65) radius 6
  circle C2 centre (-145, -65) radius 6
  circle C3 centre (-45, -65) radius 6
  point P6 (-95, -65)
  point P9 (-95, -65)
  point P8 (-145, -65)
  point P10 (-145, -65)
  point P7 (-45, -65)
  point P11 (-45, -65)
  perpendicular L1 L5
  parallel L5 L6
  coincident P6 P9
  coincident P8 P10
  coincident P7 P11
  dimension "d171" distance P6 P7 = 50
  dimension "d172" distance P6 P8 = 50
  dimension "d173" diameter C1 = 12
  dimension "d174" diameter C2 = 12
  dimension "d175" diameter C3 = 12
extrude "Extrusion47" cut sketch "Skizze37" profile of L5 L6 C1 C2 C3 against normal blind 6
sketch "Skizze38" plane through (0, 0, 10) normal (0, 0, 1) x axis (-1, 0, 0)
  line L1 (-18, -135) -> (-77, -135)
  line L2 (-15, -88) -> (-15, -132)
  line L3 (-42, -85) -> (-18, -85)
  line L4 (-45, -48) -> (-45, -82)
  line L5 (-62, -45) -> (-48, -45)
  line L6 (-65, -117) -> (-65, -48)
  line L7 (-77, -120) -> (-68, -120)
  line L8 (-80, -132) -> (-80, -123)
  line L9 (-45, -55) -> (-45, -48)
  line L10 (-26, -25) -> (-76, -25)
  line L11 (-66, -25) -> (-66, -82)
  line L12 (-66, -65) -> (-66, -25)
  line L13 (-56, -65) -> (-66, -65)
  line L14 (-66, -59) -> (-66, -65)
  line L15 (-66, -31) -> (-66, -25)
  line L16 (-51, -31) -> (-66, -31)
  line L17 (-66, -59) -> (-51, -59)
  line L18 (-66, -31) -> (-66, -59)
  line L19 (-56, -59) -> (-56, -65)
  line L20 (-56, -25) -> (-56, -31)
  line L21 (-48, -45) -> (-51, -45)
  line L22 (-51, -55) -> (-45, -55)
  line L23 (-51, -45) -> (-51, -31)
  line L24 (-51, -59) -> (-51, -55)
  circle C1 centre (-50, -50) radius 1.75
  circle C2 centre (-20, -130) radius 1.75
  circle C3 centre (-75, -127.5) radius 1.75
  circle C4 centre (-60, -50) radius 1.75
  circle C5 centre (-60, -90) radius 1.75
  circle C6 centre (-20, -90) radius 1.75
  arc A1 centre (-18, -132) radius 3 clockwise from (-15, -132) to (-18, -135)
  arc A2 centre (-18, -88) radius 3 clockwise from (-18, -85) to (-15, -88)
  arc A3 centre (-42, -82) radius 3 clockwise from (-42, -85) to (-45, -82)
  arc A4 centre (-48, -48) radius 3 clockwise from (-48, -45) to (-45, -48)
  arc A5 centre (-62, -48) radius 3 clockwise from (-65, -48) to (-62, -45)
  arc A6 centre (-68, -117) radius 3 clockwise from (-65, -117) to (-68, -120)
  arc A7 centre (-77, -123) radius 3 clockwise from (-80, -123) to (-77, -120)
  arc A8 centre (-77, -132) radius 3 clockwise from (-77, -135) to (-80, -132)
  arc A9 centre (-48, -48) radius 3 clockwise from (-48, -45) to (-45, -48)
  point P32 (-45, -55)
  point P36 (-66, -25)
  point P46 (-56, -31)
  point P47 (-51, -55)
  point P48 (-56, -59)
  point P37 (-66, -65)
  point P38 (-56, -65)
  point P39 (-56, -25)
  point P40 (-66, -59)
  point P41 (-66, -31)
  vertical L9
  horizontal L22
  coincident L4 P32
  perpendicular L9 L10
  coincident L10 P36
  perpendicular L10 L11
  perpendicular L10 L12
  perpendicular L6 L13
  perpendicular L10 L19
  perpendicular L13 L14
  perpendicular L10 L15
  horizontal L16
  vertical L23
  horizontal L17
  vertical L18
  collinear L19 L20
  coincident L16 P46
  coincident P47 L23
  coincident L17 P48
  collinear L23 L24
  tangent L9 A9
  tangent L21 A9
  dimension "d178" distance P36 P37 = 40
  dimension "d179" distance P37 P38 = 10
  dimension "d180" distance P38 P39 = 40
  dimension "d181" distance P37 P40 = 6
  dimension "d182" distance P36 P41 = 6
  dimension "d183" radius A9 = 3
extrude "Extrusion48" add sketch "Skizze38" profile of C1 C4 L4 A4 L5 A5 L6 L21 L9 L22 L11 L12 L16 L24 L17 L18 A9 along normal blind 3
sketch "Skizze39" plane through (0, 0, 13) normal (0, 0, 1) x axis (-1, 0, 0)
  line L1 (-45, -48) -> (-45, -55)
  line L2 (-51, -45) -> (-48, -45)
  line L3 (-51, -31) -> (-51, -45)
  line L4 (-66, -31) -> (-51, -31)
  line L5 (-66, -59) -> (-66, -31)
  line L6 (-51, -59) -> (-66, -59)
  line L7 (-51, -55) -> (-51, -59)
  line L8 (-45, -55) -> (-51, -55)
  line L9 (-56, -31) -> (-51, -31)
  line L10 (-56, -37) -> (-56, -31)
  line L11 (-51, -37) -> (-56, -37)
  line L12 (-51, -31) -> (-51, -37)
  line L13 (-56, -59) -> (-51, -59)
  line L14 (-56, -53) -> (-56, -59)
  line L15 (-51, -53) -> (-56, -53)
  line L16 (-51, -59) -> (-51, -53)
  circle C1 centre (-50, -50) radius 1.75
  circle C2 centre (-60, -50) radius 1.75
  arc A1 centre (-48, -48) radius 3 clockwise from (-48, -45) to (-45, -48)
  point P9 (-51, -31)
  point P14 (-51, -31)
  point P12 (-51, -59)
  point P18 (-51, -59)
  horizontal L9
  vertical L10
  horizontal L11
  vertical L12
  coincident P9 P14
  horizontal L13
  vertical L14
  horizontal L15
  vertical L16
  coincident P12 P18
extrude "Extrusion49" add sketch "Skizze39" profile of L3 L4 L6 L7 L9 L10 L11 L12 L13 L14 L15 L16 along normal blind 40
extrude "Extrusion50" add of existing geometry blind 2
extrude "Extrusion51" add of existing geometry blind 2
split "Teilen6"
combine "Kombinieren7"
extrude "Extrusion52" cut of existing geometry blind -40
extrude "Extrusion53" add sketch "Skizze38" profile of L6 L10 L11 L12 L13 L20 L14 L15 L16 L17 along normal blind 5
extrude "Extrusion54" add of existing geometry blind 6
extrude "Extrusion55" add of existing geometry blind 6
sketch "Skizze40" plane through (0, 0, 15) normal (0, 0, 1) x axis (-1, 0, 0)
  line L1 (-51, -55) -> (-51, -65)
  line L2 (-45, -55) -> (-51, -55)
  line L3 (-45, -48) -> (-45, -55)
  line L4 (-51, -45) -> (-48, -45)
  line L5 (-51, -25) -> (-51, -45)
  line L6 (-66, -25) -> (-51, -25)
  line L7 (-66, -65) -> (-66, -25)
  line L8 (-51, -65) -> (-66, -65)
  line L9 (-56, -25) -> (-51, -25)
  line L10 (-56, -31) -> (-56, -25)
  line L11 (-51, -31) -> (-56, -31)
  line L12 (-51, -25) -> (-51, -31)
  line L13 (-56, -65) -> (-51, -65)
  line L14 (-56, -59) -> (-56, -65)
  line L15 (-51, -59) -> (-56, -59)
  line L16 (-51, -65) -> (-51, -59)
  circle C1 centre (-60, -50) radius 1.75
  circle C2 centre (-50, -50) radius 1.75
  arc A1 centre (-48, -48) radius 3 clockwise from (-48, -45) to (-45, -48)
  point P11 (-51, -25)
  point P14 (-51, -25)
  point P4 (-51, -65)
  point P18 (-51, -65)
  point P15 (-56, -25)
  point P17 (-51, -31)
  point P19 (-56, -65)
  point P21 (-51, -59)
  horizontal L9
  vertical L10
  horizontal L11
  vertical L12
  coincident P11 P14
  horizontal L13
  vertical L14
  horizontal L15
  vertical L16
  coincident P4 P18
  dimension "d200" distance P14 P15 = 5
  dimension "d201" distance P14 P17 = 6
  dimension "d202" distance P18 P19 = 5
  dimension "d203" distance P18 P21 = 6
extrude "Extrusion56" add sketch "Skizze40" profile of L1 L5 L6 L8 L9 L10 L11 L12 L13 L14 L15 L16 along normal blind 40
sketch "Skizze41" plane through (56, 0, 0) normal (1, 0, 0) x axis (0, 1, 0)
  line L1 (65, 15) -> (59, 15)
  line L2 (65, 55) -> (65, 15)
  line L3 (59, 55) -> (65, 55)
  line L4 (59, 15) -> (59, 55)
  line L5 (65, 55) -> (59, 55)
  line L6 (65, 49) -> (65, 55)
  line L7 (59, 49) -> (65, 49)
  line L8 (59, 55) -> (59, 49)
  line L9 (59, 15) -> (65, 15)
  line L10 (59, 21) -> (59, 15)
  line L11 (65, 21) -> (59, 21)
  line L12 (65, 15) -> (65, 21)
  line L13 (25, 15) -> (31, 15)
  line L14 (25, 21) -> (25, 15)
  line L15 (31, 21) -> (25, 21)
  line L16 (31, 15) -> (31, 21)
  line L17 (31, 55) -> (25, 55)
  line L18 (31, 49) -> (31, 55)
  line L19 (25, 49) -> (31, 49)
  line L20 (25, 55) -> (25, 49)
  circle C1 centre (28, 52) radius 1.4
  circle C2 centre (62, 52) radius 1.4
  circle C3 centre (28, 18) radius 1.4
  circle C4 centre (62, 18) radius 1.4
  point P5 (59, 55)
  point P6 (59, 55)
  point P12 (59, 21)
  point P3 (65, 15)
  point P10 (65, 15)
  point P7 (65, 55)
  point P9 (59, 49)
  horizontal L5
  vertical L6
  horizontal L7
  vertical L8
  coincident P5 P6
  horizontal L9
  vertical L10
  horizontal L11
  vertical L12
  coincident L4 P12
  coincident P3 P10
  horizontal L13
  vertical L14
  horizontal L15
  vertical L16
  horizontal L17
  vertical L18
  horizontal L19
  vertical L20
  dimension "d206" distance P6 P7 = 6
  dimension "d207" distance P6 P9 = 6
  dimension "d208" diameter C1 = 2.8
  dimension "d209" diameter C2 = 2.8
  dimension "d210" diameter C3 = 2.8
  dimension "d211" diameter C4 = 2.8
extrude "Extrusion57" add sketch "Skizze41" profile of C1 C2 C3 C4 along normal blind 10
sketch "Skizze42" plane through (0, 0, 15) normal (0, 0, 1) x axis (-1, 0, 0)
  line L1 (-56, -59) -> (-56, -65)
  line L2 (-51, -59) -> (-56, -59)
  line L3 (-51, -55) -> (-51, -59)
  line L4 (-45, -55) -> (-51, -55)
  line L5 (-45, -48) -> (-45, -55)
  line L6 (-51, -45) -> (-48, -45)
  line L7 (-51, -31) -> (-51, -45)
  line L8 (-56, -31) -> (-51, -31)
  line L9 (-56, -25) -> (-56, -31)
  line L10 (-66, -25) -> (-56, -25)
  line L11 (-66, -65) -> (-66, -25)
  line L12 (-56, -65) -> (-66, -65)
  circle C1 centre (-50, -50) radius 1.75
  circle C2 centre (-60, -50) radius 1.75
  arc A1 centre (-48, -48) radius 3 clockwise from (-48, -45) to (-45, -48)
  circle C3 centre (-60, -50) radius 3.5
  concentric C2 C3
  dimension "d214" diameter C3 = 7
extrude "Extrusion58" cut sketch "Skizze42" profile of C2 C3 against normal blind 3
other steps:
base_feature "Basiselement"

design "Laserhalter"
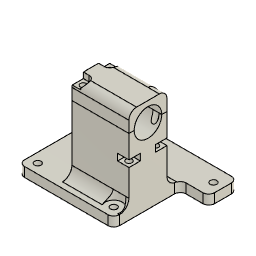
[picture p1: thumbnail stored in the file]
sketch "Skizze1" plane through (0, 0, 10) normal (0, 0, 1) x axis (-1, 0, 0)
  line L1 (-18, -135) -> (-77, -135)
  line L2 (-15, -88) -> (-15, -132)
  line L3 (-42, -85) -> (-18, -85)
  line L4 (-45, -48) -> (-45, -82)
  line L5 (-62, -45) -> (-48, -45)
  line L6 (-65, -117) -> (-65, -48)
  line L7 (-77, -120) -> (-68, -120)
  line L8 (-80, -132) -> (-80, -123)
  circle C1 centre (-75, -127.5) radius 1.75
  circle C2 centre (-60, -50) radius 1.75
  circle C3 centre (-20, -130) radius 1.75
  circle C4 centre (-50, -50) radius 1.75
  circle C5 centre (-60, -90) radius 1.75
  circle C6 centre (-20, -90) radius 1.75
  arc A1 centre (-18, -132) radius 3 clockwise from (-15, -132) to (-18, -135)
  arc A2 centre (-18, -88) radius 3 clockwise from (-18, -85) to (-15, -88)
  arc A3 centre (-42, -82) radius 3 clockwise from (-42, -85) to (-45, -82)
  arc A4 centre (-48, -48) radius 3 clockwise from (-48, -45) to (-45, -48)
  arc A5 centre (-62, -48) radius 3 clockwise from (-65, -48) to (-62, -45)
  arc A6 centre (-68, -117) radius 3 clockwise from (-65, -117) to (-68, -120)
  arc A7 centre (-77, -123) radius 3 clockwise from (-80, -123) to (-77, -120)
  arc A8 centre (-77, -132) radius 3 clockwise from (-77, -135) to (-80, -132)
extrude "Extrusion1" new body sketch "Skizze1" along normal blind 5
move "Verschieben1"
